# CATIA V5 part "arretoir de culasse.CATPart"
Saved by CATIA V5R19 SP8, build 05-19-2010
Part number: arrêtoir de culasse
Bounding box of the stored display mesh (mm): x -1 to 9.667, y -3.269 to 33.167, z -3.297 to 9.409
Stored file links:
  E:\Catia parts\GLOCK\Poignée\arretoir de culasse.CATPart
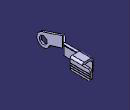
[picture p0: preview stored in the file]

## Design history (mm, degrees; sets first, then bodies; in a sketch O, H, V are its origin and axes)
Body1 (main body)
  Solid1: solid without history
